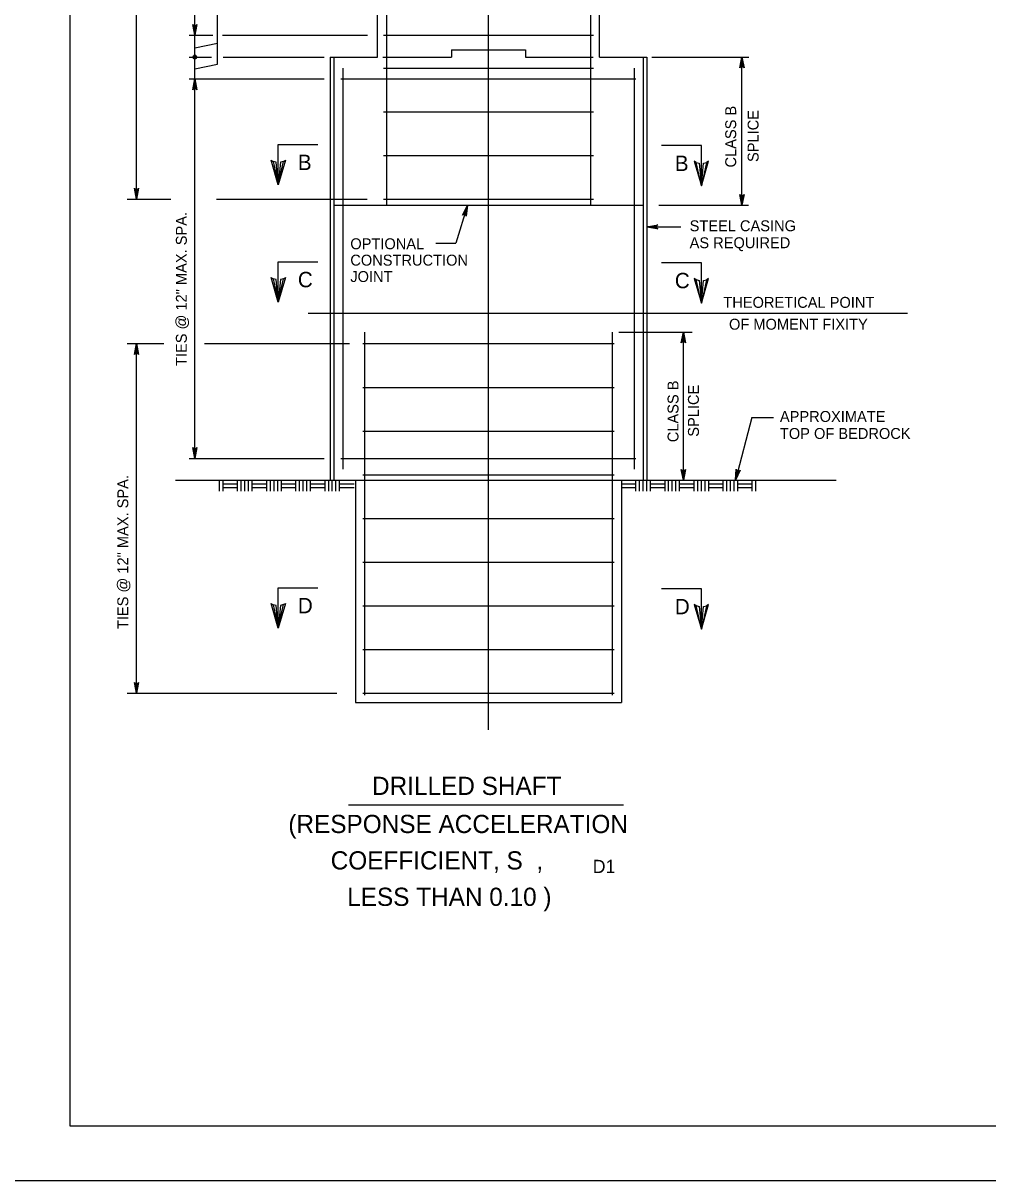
# Model space of a CAD drawing. Extents: x 646165 to 651486, y 296916 to 299292.
# Drawn here: x 649816.7 to 650081.6, y 296916.2 to 297234.1 of the extents above; entities that cross this region are included whole.
import ezdxf

# ---------------------------------------------------------------- set-up
doc = ezdxf.new("R2010")
doc.units = 0
for name, color, linetype in [('1', 7, 'Continuous'), ('2', 7, 'Continuous'), ('50', 7, 'Continuous'), ('51', 7, 'Continuous'), ('52', 7, 'Continuous'), ('53', 7, 'Continuous'), ('54', 7, 'Continuous'), ('55', 7, 'Continuous'), ('56', 7, 'Continuous'), ('PLT-BNDY', 7, 'Continuous')]:
    doc.layers.add(name, color=color, linetype=linetype)

msp = doc.modelspace()

# ---------------------------------------------------------------- linework, layer by layer
at = {"layer": '1'}
for p, q in [((649886.73, 297200.8), (649897.66, 297200.8)), ((649886.73, 297189.73), (649886.73, 297200.8)), ((650002.97, 297200.53), (649992.04, 297200.53)), ((650002.97, 297189.46), (650002.97, 297200.53)), ((649886.73, 297168.6), (649897.66, 297168.6)), ((649886.73, 297157.53), (649886.73, 297168.6)), ((650002.97, 297168.34), (649992.04, 297168.34)), ((650002.97, 297157.27), (650002.97, 297168.34)), ((649886.73, 297079.09), (649897.66, 297079.09)), ((649886.73, 297068.03), (649886.73, 297079.09)), ((650002.97, 297078.83), (649992.04, 297078.83)), ((650002.97, 297067.76), (650002.97, 297078.83))]:
    msp.add_line(p, q, dxfattribs=at)
for points in [[(649888.21, 297196.15), (649887.36, 297195.91), (649886.73, 297189.73), (649888.21, 297196.15), (649888.72, 297196.48), (649886.73, 297189.73), (649886.18, 297195.9), (649885.34, 297196.13), (649886.73, 297189.73), (649884.78, 297196.48), (649885.34, 297196.13)], [(650001.5, 297195.88), (650002.34, 297195.64), (650002.97, 297189.46), (650001.5, 297195.88), (650000.98, 297196.21), (650002.97, 297189.46), (650003.53, 297195.64), (650004.36, 297195.86), (650002.97, 297189.46), (650004.92, 297196.21), (650004.36, 297195.86)], [(649888.21, 297163.95), (649887.36, 297163.72), (649886.73, 297157.53), (649888.21, 297163.95), (649888.72, 297164.28), (649886.73, 297157.53), (649886.18, 297163.71), (649885.34, 297163.94), (649886.73, 297157.53), (649884.78, 297164.28), (649885.34, 297163.94)], [(650001.5, 297163.69), (650002.34, 297163.45), (650002.97, 297157.27), (650001.5, 297163.69), (650000.98, 297164.02), (650002.97, 297157.27), (650003.53, 297163.44), (650004.36, 297163.67), (650002.97, 297157.27), (650004.92, 297164.02), (650004.36, 297163.67)], [(649888.21, 297074.45), (649887.36, 297074.21), (649886.73, 297068.03), (649888.21, 297074.45), (649888.72, 297074.78), (649886.73, 297068.03), (649886.18, 297074.2), (649885.34, 297074.43), (649886.73, 297068.03), (649884.78, 297074.78), (649885.34, 297074.43)], [(650001.5, 297074.18), (650002.34, 297073.94), (650002.97, 297067.76), (650001.5, 297074.18), (650000.98, 297074.51), (650002.97, 297067.76), (650003.53, 297073.94), (650004.36, 297074.16), (650002.97, 297067.76), (650004.92, 297074.51), (650004.36, 297074.16)]]:
    msp.add_lwpolyline(points, dxfattribs=at)
at = {"layer": '2'}
for p, q in [((649829.59, 296931.25), (649829.59, 297495.25)), ((650615.59, 296931.25), (649829.59, 296931.25))]:
    msp.add_line(p, q, dxfattribs=at)
at = {"layer": '50'}
msp.add_line((649944.48, 297040.08), (649944.48, 297419.54), dxfattribs=at)
at = {"layer": '51'}
for p, q in [((649913.98, 297224.79), (649913.98, 297405.84)), ((649974.98, 297224.79), (649974.98, 297405.84)), ((649901.98, 297224.79), (649913.98, 297224.79)), ((649915.47, 297224.79), (649934.3, 297224.79)), ((649934.3, 297226.79), (649954.66, 297226.79)), ((649934.3, 297226.79), (649934.3, 297224.79)), ((649954.66, 297226.79), (649954.66, 297224.79)), ((649954.66, 297224.79), (649973.25, 297224.79)), ((649974.98, 297224.79), (649986.98, 297224.79)), ((649901.98, 297184.12), (649986.98, 297184.12)), ((649901.98, 297108.62), (649907.98, 297108.62)), ((649907.98, 297108.62), (649907.98, 297047.62)), ((649980.98, 297108.62), (649986.98, 297108.62)), ((649980.98, 297108.62), (649980.98, 297047.62)), ((649907.98, 297047.62), (649980.98, 297047.62))]:
    msp.add_line(p, q, dxfattribs=at)
at = {"layer": '52'}
for p, q in [((649847.85, 297185.79), (649847.85, 297399.84)), ((649870.06, 297222.89), (649870.06, 297275.07)), ((649863.85, 297114.62), (649863.85, 297238.4)), ((649862.28, 297230.79), (649868.83, 297230.79)), ((649863.85, 297227.34), (649870.06, 297228.66)), ((649871.43, 297230.79), (649911.28, 297230.79)), ((649862.28, 297224.79), (649868.43, 297224.79)), ((649871.64, 297224.79), (649899.38, 297224.79)), ((649989.32, 297224.79), (650015.98, 297224.79)), ((650014.1, 297184.12), (650014.1, 297224.79)), ((649863.85, 297221.57), (649870.06, 297222.89)), ((649862.28, 297218.79), (649899.38, 297218.79)), ((649845.26, 297185.79), (649857.28, 297185.79)), ((649869.77, 297185.79), (649911.17, 297185.79)), ((649938.72, 297184.12), (649935.55, 297173.67)), ((649991.3, 297184.12), (650015.85, 297184.12)), ((649987.98, 297178.16), (649997.33, 297178.16)), ((649930.03, 297173.67), (649935.55, 297173.67)), ((649894.96, 297154.51), (650059.57, 297154.51)), ((649980.28, 297149.28), (650000.41, 297149.28)), ((649998.01, 297108.62), (649998.01, 297149.28)), ((649845.26, 297146.12), (649855.35, 297146.12)), ((649847.85, 297050.12), (649847.85, 297146.12)), ((649866.52, 297146.12), (649906.33, 297146.12)), ((650016.84, 297125.8), (650012.3, 297108.62)), ((650016.84, 297125.8), (650022.73, 297125.8)), ((649862.28, 297114.62), (649899.38, 297114.62)), ((649845.26, 297050.12), (649902.86, 297050.12))]:
    msp.add_line(p, q, dxfattribs=at)
for points in [[(649863.85, 297230.79), (649863.3, 297233.77), (649863.37, 297233.66), (649863.45, 297233.54), (649863.55, 297233.48), (649863.65, 297233.42), (649863.75, 297233.41), (649863.85, 297233.39), (649863.95, 297233.41), (649864.05, 297233.42), (649864.15, 297233.48), (649864.25, 297233.54), (649864.33, 297233.66), (649864.41, 297233.77), (649863.85, 297230.79), (649864.33, 297233.66), (649864.25, 297233.54), (649863.85, 297230.79), (649864.15, 297233.48), (649864.05, 297233.42), (649863.85, 297230.79), (649863.95, 297233.41), (649863.85, 297233.39), (649863.85, 297230.79), (649863.75, 297233.41), (649863.65, 297233.42), (649863.85, 297230.79), (649863.55, 297233.48), (649863.45, 297233.54), (649863.85, 297230.79), (649863.37, 297233.66)], [(650014.1, 297224.79), (650014.66, 297221.81), (650014.58, 297221.92), (650014.5, 297222.04), (650014.4, 297222.1), (650014.3, 297222.15), (650014.2, 297222.17), (650014.1, 297222.19), (650014, 297222.17), (650013.9, 297222.15), (650013.8, 297222.1), (650013.7, 297222.04), (650013.62, 297221.92), (650013.55, 297221.81), (650014.1, 297224.79), (650013.62, 297221.92), (650013.7, 297222.04), (650014.1, 297224.79), (650013.8, 297222.1), (650013.9, 297222.15), (650014.1, 297224.79), (650014, 297222.17), (650014.1, 297222.19), (650014.1, 297224.79), (650014.2, 297222.17), (650014.3, 297222.15), (650014.1, 297224.79), (650014.4, 297222.1), (650014.5, 297222.04), (650014.1, 297224.79), (650014.58, 297221.92)], [(649863.85, 297218.79), (649864.41, 297215.81), (649864.33, 297215.92), (649864.25, 297216.04), (649864.15, 297216.1), (649864.05, 297216.15), (649863.95, 297216.17), (649863.85, 297216.19), (649863.75, 297216.17), (649863.65, 297216.15), (649863.55, 297216.1), (649863.45, 297216.04), (649863.37, 297215.92), (649863.3, 297215.81), (649863.85, 297218.79), (649863.37, 297215.92), (649863.45, 297216.04), (649863.85, 297218.79), (649863.55, 297216.1), (649863.65, 297216.15), (649863.85, 297218.79), (649863.75, 297216.17), (649863.85, 297216.19), (649863.85, 297218.79), (649863.95, 297216.17), (649864.05, 297216.15), (649863.85, 297218.79), (649864.15, 297216.1), (649864.25, 297216.04), (649863.85, 297218.79), (649864.33, 297215.92)], [(649847.85, 297185.79), (649847.3, 297188.77), (649847.37, 297188.66), (649847.45, 297188.54), (649847.55, 297188.48), (649847.65, 297188.42), (649847.75, 297188.41), (649847.85, 297188.39), (649847.95, 297188.41), (649848.05, 297188.42), (649848.15, 297188.48), (649848.25, 297188.54), (649848.33, 297188.66), (649848.41, 297188.77), (649847.85, 297185.79), (649848.33, 297188.66), (649848.25, 297188.54), (649847.85, 297185.79), (649848.15, 297188.48), (649848.05, 297188.42), (649847.85, 297185.79), (649847.95, 297188.41), (649847.85, 297188.39), (649847.85, 297185.79), (649847.75, 297188.41), (649847.65, 297188.42), (649847.85, 297185.79), (649847.55, 297188.48), (649847.45, 297188.54), (649847.85, 297185.79), (649847.37, 297188.66)], [(650014.1, 297184.12), (650013.55, 297187.1), (650013.62, 297186.99), (650013.7, 297186.87), (650013.8, 297186.81), (650013.9, 297186.76), (650014, 297186.74), (650014.1, 297186.72), (650014.2, 297186.74), (650014.3, 297186.76), (650014.4, 297186.81), (650014.5, 297186.87), (650014.58, 297186.99), (650014.66, 297187.1), (650014.1, 297184.12), (650014.58, 297186.99), (650014.5, 297186.87), (650014.1, 297184.12), (650014.4, 297186.81), (650014.3, 297186.76), (650014.1, 297184.12), (650014.2, 297186.74), (650014.1, 297186.72), (650014.1, 297184.12), (650014, 297186.74), (650013.9, 297186.76), (650014.1, 297184.12), (650013.8, 297186.81), (650013.7, 297186.87), (650014.1, 297184.12), (650013.62, 297186.99)], [(649938.72, 297184.12), (649938.39, 297181.1), (649938.31, 297181.37), (649938.15, 297181.54), (649937.97, 297181.63), (649937.77, 297181.66), (649937.54, 297181.6), (649937.32, 297181.43), (649938.72, 297184.12), (649937.54, 297181.6), (649937.77, 297181.66), (649938.72, 297184.12), (649937.97, 297181.63), (649938.15, 297181.54), (649938.72, 297184.12), (649938.31, 297181.37)], [(649987.98, 297178.16), (649990.96, 297178.72), (649990.73, 297178.56), (649990.61, 297178.36), (649990.58, 297178.16), (649990.61, 297177.96), (649990.73, 297177.76), (649990.96, 297177.6), (649987.98, 297178.16), (649990.73, 297177.76), (649990.61, 297177.96), (649987.98, 297178.16), (649990.58, 297178.16), (649990.61, 297178.36), (649987.98, 297178.16), (649990.73, 297178.56)], [(649998.01, 297149.28), (649998.57, 297146.3), (649998.49, 297146.42), (649998.41, 297146.53), (649998.31, 297146.59), (649998.21, 297146.65), (649998.11, 297146.67), (649998.01, 297146.68), (649997.91, 297146.67), (649997.81, 297146.65), (649997.71, 297146.59), (649997.61, 297146.53), (649997.53, 297146.42), (649997.45, 297146.3), (649998.01, 297149.28), (649997.53, 297146.42), (649997.61, 297146.53), (649998.01, 297149.28), (649997.71, 297146.59), (649997.81, 297146.65), (649998.01, 297149.28), (649997.91, 297146.67), (649998.01, 297146.68), (649998.01, 297149.28), (649998.11, 297146.67), (649998.21, 297146.65), (649998.01, 297149.28), (649998.31, 297146.59), (649998.41, 297146.53), (649998.01, 297149.28), (649998.49, 297146.42)], [(649847.85, 297146.12), (649848.41, 297143.13), (649848.33, 297143.25), (649848.25, 297143.36), (649848.15, 297143.42), (649848.05, 297143.48), (649847.95, 297143.5), (649847.85, 297143.52), (649847.75, 297143.5), (649847.65, 297143.48), (649847.55, 297143.42), (649847.45, 297143.36), (649847.37, 297143.25), (649847.3, 297143.13), (649847.85, 297146.12), (649847.37, 297143.25), (649847.45, 297143.36), (649847.85, 297146.12), (649847.55, 297143.42), (649847.65, 297143.48), (649847.85, 297146.12), (649847.75, 297143.5), (649847.85, 297143.52), (649847.85, 297146.12), (649847.95, 297143.5), (649848.05, 297143.48), (649847.85, 297146.12), (649848.15, 297143.42), (649848.25, 297143.36), (649847.85, 297146.12), (649848.33, 297143.25)], [(649863.85, 297114.62), (649863.3, 297117.6), (649863.37, 297117.48), (649863.45, 297117.37), (649863.55, 297117.31), (649863.65, 297117.25), (649863.75, 297117.23), (649863.85, 297117.22), (649863.95, 297117.23), (649864.05, 297117.25), (649864.15, 297117.31), (649864.25, 297117.37), (649864.33, 297117.48), (649864.41, 297117.6), (649863.85, 297114.62), (649864.33, 297117.48), (649864.25, 297117.37), (649863.85, 297114.62), (649864.15, 297117.31), (649864.05, 297117.25), (649863.85, 297114.62), (649863.95, 297117.23), (649863.85, 297117.22), (649863.85, 297114.62), (649863.75, 297117.23), (649863.65, 297117.25), (649863.85, 297114.62), (649863.55, 297117.31), (649863.45, 297117.37), (649863.85, 297114.62), (649863.37, 297117.48)], [(649998.01, 297108.62), (649997.45, 297111.6), (649997.53, 297111.48), (649997.61, 297111.37), (649997.71, 297111.31), (649997.81, 297111.25), (649997.91, 297111.23), (649998.01, 297111.22), (649998.11, 297111.23), (649998.21, 297111.25), (649998.31, 297111.31), (649998.41, 297111.37), (649998.49, 297111.48), (649998.57, 297111.6), (649998.01, 297108.62), (649998.49, 297111.48), (649998.41, 297111.37), (649998.01, 297108.62), (649998.31, 297111.31), (649998.21, 297111.25), (649998.01, 297108.62), (649998.11, 297111.23), (649998.01, 297111.22), (649998.01, 297108.62), (649997.91, 297111.23), (649997.81, 297111.25), (649998.01, 297108.62), (649997.71, 297111.31), (649997.61, 297111.37), (649998.01, 297108.62), (649997.53, 297111.48)], [(650012.3, 297108.62), (650012.52, 297111.64), (650012.57, 297111.51), (650012.61, 297111.38), (650012.7, 297111.3), (650012.78, 297111.21), (650012.87, 297111.17), (650012.96, 297111.13), (650013.06, 297111.12), (650013.16, 297111.11), (650013.28, 297111.14), (650013.39, 297111.18), (650013.49, 297111.27), (650013.6, 297111.36), (650012.3, 297108.62), (650013.49, 297111.27), (650013.39, 297111.18), (650012.3, 297108.62), (650013.28, 297111.14), (650013.16, 297111.11), (650012.3, 297108.62), (650013.06, 297111.12), (650012.96, 297111.13), (650012.3, 297108.62), (650012.87, 297111.17), (650012.78, 297111.21), (650012.3, 297108.62), (650012.7, 297111.3), (650012.61, 297111.38), (650012.3, 297108.62), (650012.57, 297111.51)], [(649847.85, 297050.12), (649847.3, 297053.1), (649847.37, 297052.98), (649847.45, 297052.87), (649847.55, 297052.81), (649847.65, 297052.75), (649847.75, 297052.73), (649847.85, 297052.72), (649847.95, 297052.73), (649848.05, 297052.75), (649848.15, 297052.81), (649848.25, 297052.87), (649848.33, 297052.98), (649848.41, 297053.1), (649847.85, 297050.12), (649848.33, 297052.98), (649848.25, 297052.87), (649847.85, 297050.12), (649848.15, 297052.81), (649848.05, 297052.75), (649847.85, 297050.12), (649847.95, 297052.73), (649847.85, 297052.72), (649847.85, 297050.12), (649847.75, 297052.73), (649847.65, 297052.75), (649847.85, 297050.12), (649847.55, 297052.81), (649847.45, 297052.87), (649847.85, 297050.12), (649847.37, 297052.98)]]:
    msp.add_lwpolyline(points, dxfattribs=at)
for radius in [0.533, 0.267]:
    msp.add_circle((649863.85, 297224.79), radius, dxfattribs=at)
at = {"layer": '53'}
msp.add_line((649906.04, 297019.46), (649981.57, 297019.46), dxfattribs=at)
at = {"layer": '54'}
for p, q in [((649916.48, 297325.94), (649916.48, 297184.12)), ((649972.48, 297292.61), (649972.48, 297184.12)), ((649915.64, 297230.79), (649973.31, 297230.79)), ((649904.48, 297221.79), (649904.48, 297111.62)), ((649915.64, 297221.79), (649973.31, 297221.79)), ((649984.48, 297221.79), (649984.48, 297111.62)), ((649903.98, 297218.79), (649984.98, 297218.79)), ((649915.64, 297209.79), (649973.31, 297209.79)), ((649915.64, 297197.79), (649973.31, 297197.79)), ((649915.64, 297185.79), (649973.31, 297185.79)), ((649910.48, 297149.28), (649910.48, 297049.62)), ((649978.48, 297149.28), (649978.48, 297049.62)), ((649909.98, 297146.12), (649978.98, 297146.12)), ((649909.98, 297134.12), (649978.98, 297134.12)), ((649909.98, 297122.12), (649978.98, 297122.12)), ((649903.98, 297114.62), (649984.98, 297114.62)), ((649909.98, 297110.12), (649978.98, 297110.12)), ((649909.98, 297098.12), (649978.98, 297098.12)), ((649909.98, 297086.12), (649978.98, 297086.12)), ((649909.98, 297074.12), (649978.98, 297074.12)), ((649909.98, 297062.12), (649978.98, 297062.12)), ((649909.98, 297050.12), (649978.98, 297050.12))]:
    msp.add_line(p, q, dxfattribs=at)
at = {"layer": '55'}
for p, q in [((649900.98, 297224.79), (649900.98, 297108.62)), ((649900.98, 297224.79), (649901.98, 297224.79)), ((649901.98, 297224.79), (649901.98, 297108.62)), ((649986.98, 297224.79), (649986.98, 297108.62)), ((649986.98, 297224.79), (649987.98, 297224.79)), ((649987.98, 297224.79), (649987.98, 297108.62)), ((649900.98, 297108.62), (649901.98, 297108.62)), ((649986.98, 297108.62), (649987.98, 297108.62))]:
    msp.add_line(p, q, dxfattribs=at)
at = {"layer": '56'}
for p, q in [((649866.89, 297230.63), (649866.85, 297230.67)), ((649858.58, 297108.62), (650039.96, 297108.62)), ((649870.61, 297105.65), (649870.61, 297108.62)), ((649871.61, 297105.65), (649871.61, 297108.62)), ((649871.61, 297107.62), (649875.61, 297107.62)), ((649875.61, 297105.65), (649875.61, 297108.62)), ((649876.61, 297105.65), (649876.61, 297108.62)), ((649877.61, 297105.65), (649877.61, 297108.62)), ((649878.61, 297105.65), (649878.61, 297108.62)), ((649879.61, 297105.65), (649879.61, 297108.62)), ((649879.61, 297107.62), (649883.61, 297107.62)), ((649883.61, 297105.65), (649883.61, 297108.62)), ((649884.61, 297105.65), (649884.61, 297108.62)), ((649885.61, 297105.65), (649885.61, 297108.62)), ((649886.61, 297105.65), (649886.61, 297108.62)), ((649887.61, 297105.65), (649887.61, 297108.62)), ((649887.61, 297107.62), (649891.61, 297107.62)), ((649891.61, 297105.65), (649891.61, 297108.62)), ((649892.61, 297105.65), (649892.61, 297108.62)), ((649893.61, 297105.65), (649893.61, 297108.62)), ((649894.61, 297105.65), (649894.61, 297108.62)), ((649895.61, 297105.65), (649895.61, 297108.62)), ((649895.61, 297107.62), (649899.61, 297107.62)), ((649899.61, 297105.65), (649899.61, 297108.62)), ((649900.61, 297105.65), (649900.61, 297108.62)), ((649901.61, 297105.65), (649901.61, 297108.62)), ((649902.61, 297105.65), (649902.61, 297108.62)), ((649903.61, 297105.65), (649903.61, 297108.62)), ((649903.61, 297107.62), (649907.61, 297107.62)), ((649980.97, 297107.62), (649984.97, 297107.62)), ((649984.97, 297105.65), (649984.97, 297108.62)), ((649985.97, 297105.65), (649985.97, 297108.62)), ((649986.97, 297105.65), (649986.97, 297108.62)), ((649987.97, 297105.65), (649987.97, 297108.62)), ((649988.97, 297105.65), (649988.97, 297108.62)), ((649988.97, 297107.62), (649992.97, 297107.62)), ((649992.97, 297105.65), (649992.97, 297108.62)), ((649993.97, 297105.65), (649993.97, 297108.62)), ((649994.97, 297105.65), (649994.97, 297108.62)), ((649995.97, 297105.65), (649995.97, 297108.62)), ((649996.97, 297105.65), (649996.97, 297108.62)), ((649996.97, 297107.62), (650000.97, 297107.62)), ((650000.97, 297105.65), (650000.97, 297108.62)), ((650001.97, 297105.65), (650001.97, 297108.62)), ((650002.97, 297105.65), (650002.97, 297108.62)), ((650003.97, 297105.65), (650003.97, 297108.62)), ((650004.97, 297105.65), (650004.97, 297108.62)), ((650004.97, 297107.62), (650008.97, 297107.62)), ((650008.97, 297105.65), (650008.97, 297108.62)), ((650009.97, 297105.65), (650009.97, 297108.62)), ((650010.97, 297105.65), (650010.97, 297108.62)), ((650011.97, 297105.65), (650011.97, 297108.62)), ((650012.97, 297105.65), (650012.97, 297108.62)), ((650012.97, 297107.62), (650016.97, 297107.62)), ((650016.91, 297105.65), (650016.91, 297108.62)), ((650017.91, 297105.65), (650017.91, 297108.62)), ((649871.61, 297106.62), (649875.61, 297106.62)), ((649879.61, 297106.62), (649883.61, 297106.62)), ((649887.61, 297106.62), (649891.61, 297106.62)), ((649895.61, 297106.62), (649899.61, 297106.62)), ((649903.61, 297106.62), (649907.61, 297106.62)), ((649980.97, 297106.62), (649984.97, 297106.62)), ((649988.97, 297106.62), (649992.97, 297106.62)), ((649996.97, 297106.62), (650000.97, 297106.62)), ((650004.97, 297106.62), (650008.97, 297106.62)), ((650012.97, 297106.62), (650016.91, 297106.62))]:
    msp.add_line(p, q, dxfattribs=at)
at = {"layer": 'PLT-BNDY'}
msp.add_lwpolyline([(649789.59, 297510.25), (650630.59, 297510.25), (650630.59, 296916.25), (649789.59, 296916.25)], close=True, dxfattribs=at)

# ---------------------------------------------------------------- texts
at = {"layer": '1'}
for s, p in [('B', (649892.15, 297193.78)), ('B', (649995.67, 297193.51)), ('C', (649892.15, 297161.59)), ('C', (649995.67, 297161.32)), ('D', (649892.15, 297072.08)), ('D', (649995.67, 297071.81))]:
    msp.add_text(s, height=4.23, dxfattribs=at).set_placement(p)
at = {"layer": '53'}
for s, p in [('CLASS B', (650012.51, 297194.48)), ('SPLICE', (650018.66, 297195.99)), ('TIES @ 12" MAX. SPA.', (649861.65, 297139.98)), ('CLASS B', (649996.67, 297119.05)), ('SPLICE', (650002.27, 297120.56)), ('TIES @ 12" MAX. SPA.', (649845.57, 297067.75))]:
    msp.add_text(s, height=3, rotation=90, dxfattribs=at).set_placement(p)
for s, height, p in [('STEEL CASING', 3, (649999.73, 297176.98)), ('OPTIONAL', 3, (649906.55, 297172.04)), ('AS REQUIRED', 3, (649999.73, 297172.32)), ('CONSTRUCTION', 3, (649906.55, 297167.54)), ('JOINT', 3, (649906.55, 297163.04)), ('THEORETICAL POINT', 3, (650008.99, 297155.95)), ('OF MOMENT FIXITY', 3, (650010.54, 297149.95)), ('APPROXIMATE ', 3, (650024.52, 297124.62)), ('TOP OF BEDROCK', 3, (650024.52, 297119.95)), ('DRILLED SHAFT', 5, (649912.52, 297022.2)), ('(RESPONSE ACCELERATION', 5, (649889.53, 297011.74)), ('COEFFICIENT, S  ,', 5, (649901.16, 297001.74)), ('D1', 3.63, (649973.12, 297000.76)), ('LESS THAN 0.10 )', 5, (649905.69, 296991.74))]:
    msp.add_text(s, height=height, dxfattribs=at).set_placement(p)

doc.saveas('drawing.dxf')
